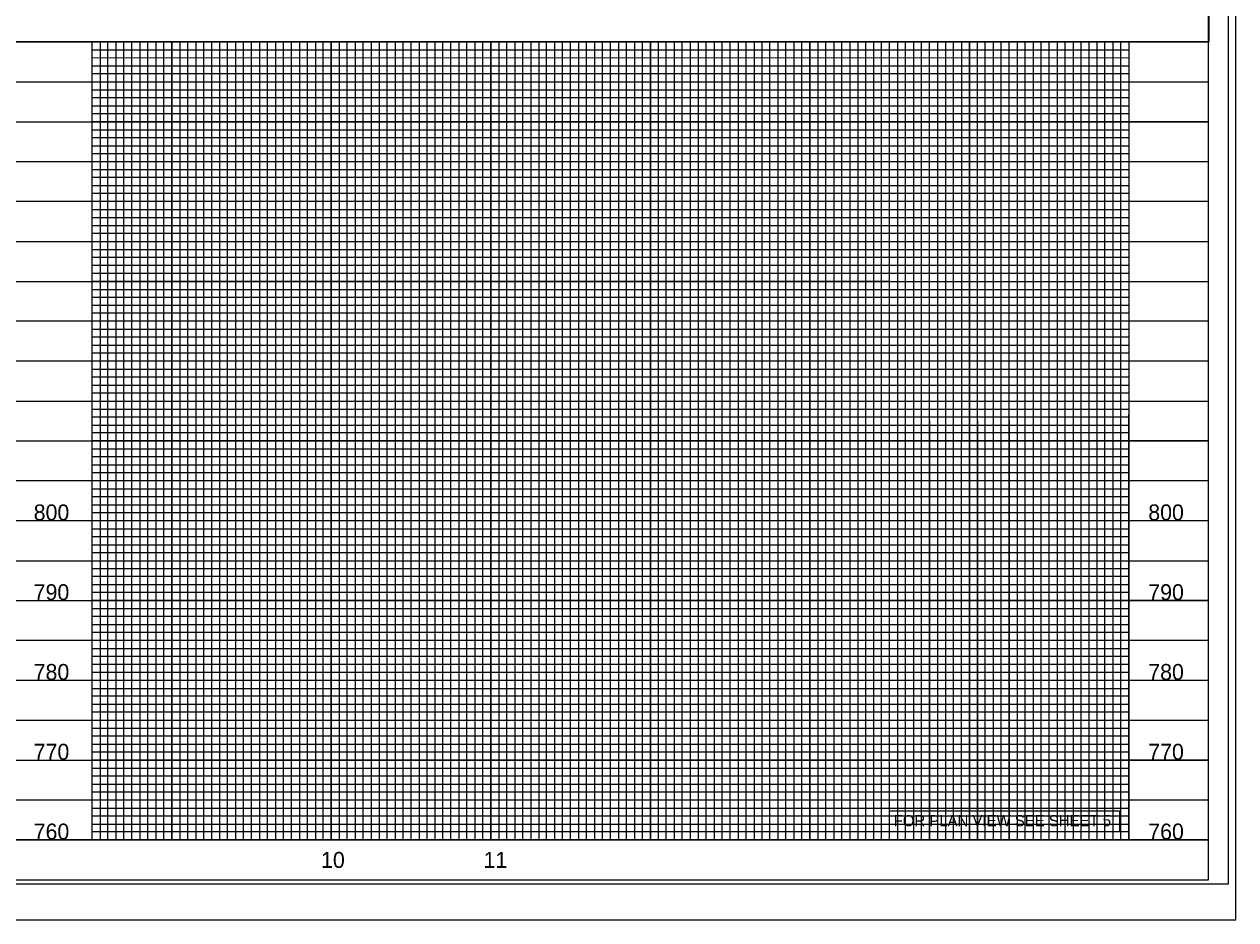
# Model space of a CAD drawing. Extents: x 1755181 to 1757273, y 729911 to 735411.
# Drawn here: x 1756105 to 1756865, y 729911 to 730472 of the extents above; entities that cross this region are included whole.
import ezdxf

# ---------------------------------------------------------------- set-up
doc = ezdxf.new("R2010")
doc.units = 0
for name, color, linetype in [('Exist Vertical Profile Horizontal Axis Label Major', 7, 'Continuous'), ('Exist Vertical Profile Vertical Axis Label', 7, 'Continuous'), ('Prop Grid Mask', 7, 'Continuous'), ('Prop VPI Label', 7, 'Continuous'), ('Scratch_Level_3', 7, 'Continuous'), ('Sheet Cutting Line CELL', 7, 'Continuous'), ('Sheet DOT Grid CELL', 7, 'Continuous'), ('Sheet Plot Border Inside CELL', 7, 'Continuous'), ('Sheet Plot Border Outside CELL', 7, 'Continuous'), ('Sheet Profile CELL', 7, 'Continuous'), ('Sheet Profile Grid Major CELL', 7, 'Continuous'), ('Sheet Profile Grid Middle CELL', 7, 'Continuous'), ('Sheet Profile Grid Minor CELL', 7, 'Continuous')]:
    doc.layers.add(name, color=color, linetype=linetype)

msp = doc.modelspace()

# ---------------------------------------------------------------- linework, layer by layer
at = {"layer": 'Prop Grid Mask'}
msp.add_lwpolyline([(1756647.67, 729978.99), (1756791.8, 729978.99), (1756791.8, 729965.78), (1756647.67, 729965.78)], close=True, dxfattribs=at)
at = {"layer": 'Scratch_Level_3'}
for points in [[(1756097.67, 730460.78), (1756097.67, 730985.78), (1756647.63, 730985.78), (1756647.63, 730752.66), (1756847.68, 730752.66), (1756847.68, 730460.78)], [(1756097.67, 729960.78), (1756847.67, 729960.78), (1756847.67, 730460.78), (1756097.67, 730460.78)]]:
    msp.add_lwpolyline(points, close=True, dxfattribs=at)
at = {"layer": 'Sheet Cutting Line CELL'}
msp.add_line((1755180.67, 729910.78), (1756864.67, 729910.78), dxfattribs=at)
at = {"layer": 'Sheet DOT Grid CELL'}
for p, q in [((1755347.67, 730460.78), (1756847.56, 730460.78)), ((1756147.67, 729960.78), (1756147.67, 730460.78)), ((1756197.67, 729960.78), (1756197.67, 730460.78)), ((1756247.67, 729960.78), (1756247.67, 730460.78)), ((1756297.67, 729960.78), (1756297.67, 730460.78)), ((1756347.67, 729960.78), (1756347.67, 730460.78)), ((1756397.67, 729960.78), (1756397.67, 730460.78)), ((1756447.67, 729960.78), (1756447.67, 730460.78)), ((1756497.67, 729960.78), (1756497.67, 730460.78)), ((1756547.67, 729960.78), (1756547.67, 730460.78)), ((1756597.67, 729960.78), (1756597.67, 730460.78)), ((1756697.67, 729960.78), (1756697.67, 730460.78)), ((1756747.67, 729960.78), (1756747.67, 730460.78)), ((1756847.66, 730410.78), (1756147.67, 730410.78)), ((1756647.62, 730360.78), (1756147.67, 730360.78)), ((1756647.67, 729960.78), (1756647.67, 730323.23)), ((1756647.67, 730310.78), (1756147.67, 730310.78)), ((1756797.67, 729960.78), (1756797.67, 730227.66)), ((1756847.67, 730210.78), (1756147.67, 730210.78)), ((1756847.67, 730160.78), (1756147.67, 730160.78)), ((1756847.67, 730110.78), (1756147.67, 730110.78)), ((1756847.67, 730060.78), (1756147.67, 730060.78)), ((1756847.67, 730010.78), (1756147.67, 730010.78))]:
    msp.add_line(p, q, dxfattribs=at)
at = {"layer": 'Sheet Plot Border Inside CELL'}
msp.add_lwpolyline([(1755193.67, 729933.23), (1756860.17, 729933.23), (1756860.17, 730988.33), (1755193.67, 730988.33)], close=True, dxfattribs=at)
at = {"layer": 'Sheet Plot Border Outside CELL'}
msp.add_lwpolyline([(1755180.67, 729910.78), (1756864.67, 729910.78), (1756864.67, 731010.78), (1755180.67, 731010.78)], close=True, dxfattribs=at)
at = {"layer": 'Sheet Profile CELL'}
for p, q in [((1755347.67, 730460.78), (1756847.67, 730460.78)), ((1756847.67, 729960.78), (1755347.67, 729960.78)), ((1755347.67, 729935.78), (1756847.67, 729935.78))]:
    msp.add_line(p, q, dxfattribs=at)
msp.add_lwpolyline([(1756847.67, 730985.78), (1755347.67, 730985.78), (1755347.67, 729935.78), (1756847.67, 729935.78)], close=True, dxfattribs=at)
at = {"layer": 'Sheet Profile Grid Major CELL'}
for p, q in [((1756147.67, 730460.78), (1756197.67, 730460.78)), ((1756247.67, 730460.78), (1756297.67, 730460.78)), ((1756347.67, 730460.78), (1756397.67, 730460.78)), ((1756447.67, 730460.78), (1756497.67, 730460.78)), ((1756547.67, 730460.78), (1756597.67, 730460.78)), ((1756647.67, 730460.78), (1756697.67, 730460.78)), ((1756747.67, 730460.78), (1756797.67, 730460.78)), ((1756747.47, 729960.67), (1756747.47, 729960.67))]:
    msp.add_line(p, q, dxfattribs=at)
for points in [[(1756097.67, 729960.78), (1756147.67, 729960.78), (1756147.67, 730460.78), (1756197.67, 730460.78), (1756197.67, 729960.78), (1756247.67, 729960.78), (1756247.67, 730460.78), (1756297.67, 730460.78), (1756297.67, 729960.78), (1756347.67, 729960.78), (1756347.67, 730460.78), (1756397.67, 730460.78), (1756397.67, 729960.78), (1756447.67, 729960.78), (1756447.67, 730460.78), (1756497.67, 730460.78), (1756497.67, 729960.78), (1756547.67, 729960.78), (1756547.67, 730460.78), (1756597.67, 730460.78), (1756597.67, 729960.78), (1756647.67, 729960.78), (1756647.67, 730460.78), (1756673.97, 730460.78)], [(1756697.67, 730460.78), (1756697.67, 729960.78), (1756747.67, 729960.78), (1756747.67, 729960.78), (1756747.67, 730460.78)], [(1756797.67, 730460.78), (1756797.67, 729960.78), (1756847.67, 729960.78), (1756847.67, 730310.78)], [(1755347.67, 730410.78), (1756847.71, 730410.78)], [(1756847.71, 730360.78), (1755347.67, 730360.78), (1755347.67, 730310.78), (1756847.71, 730310.78)], [(1756847.67, 730260.78), (1755347.67, 730260.78), (1755347.67, 730210.78), (1756847.67, 730210.78)], [(1756847.67, 730160.78), (1755347.67, 730160.78), (1755347.67, 730110.78), (1756847.67, 730110.78)], [(1756847.67, 730060.78), (1755347.67, 730060.78), (1755347.67, 730060.78), (1755347.67, 730010.78), (1756847.67, 730010.78)], [(1756847.67, 729960.78), (1755347.67, 729960.78)]]:
    msp.add_lwpolyline(points, dxfattribs=at)
at = {"layer": 'Sheet Profile Grid Middle CELL'}
for p, q in [((1756172.67, 729960.78), (1756172.67, 730460.78)), ((1756222.67, 730460.78), (1756222.67, 729960.78)), ((1756272.67, 729960.78), (1756272.67, 730460.78)), ((1756322.67, 730460.78), (1756322.67, 729960.78)), ((1756372.67, 729960.78), (1756372.67, 730460.78)), ((1756422.67, 730460.78), (1756422.67, 729960.78)), ((1756472.67, 729960.78), (1756472.67, 730460.78)), ((1756522.67, 730460.78), (1756522.67, 729960.78)), ((1756572.67, 729960.78), (1756572.67, 730460.78)), ((1756622.67, 730460.78), (1756622.67, 729960.78)), ((1756672.67, 729960.78), (1756672.67, 730460.78)), ((1755347.67, 730435.78), (1756847.66, 730435.78))]:
    msp.add_line(p, q, dxfattribs=at)
for points in [[(1756672.67, 730223.58), (1756672.67, 729960.78), (1756722.67, 729960.78), (1756722.67, 730460.78)], [(1756722.67, 730223.58), (1756722.67, 729960.78), (1756772.67, 729960.78), (1756772.67, 730460.78)], [(1756847.71, 730385.78), (1755347.67, 730385.78), (1755347.67, 730335.78), (1756847.71, 730335.78)], [(1756847.66, 730285.78), (1755347.67, 730285.78), (1755347.67, 730235.78), (1756847.67, 730235.78)], [(1756847.67, 730185.78), (1755347.67, 730185.78), (1755347.67, 730135.78), (1756847.67, 730135.78)], [(1756847.67, 730085.78), (1755347.67, 730085.78), (1755347.67, 730035.78), (1756847.67, 730035.78)], [(1756847.67, 729985.78), (1755347.67, 729985.78)]]:
    msp.add_lwpolyline(points, dxfattribs=at)
at = {"layer": 'Sheet Profile Grid Minor CELL'}
for p, q in [((1756152.67, 730460.78), (1756152.67, 729960.78)), ((1756157.67, 729960.78), (1756157.67, 730460.78)), ((1756162.67, 730460.78), (1756162.67, 729960.78)), ((1756167.67, 729960.78), (1756167.67, 730460.78)), ((1756177.67, 730460.78), (1756177.67, 729960.78)), ((1756182.67, 729960.78), (1756182.67, 730460.78)), ((1756187.67, 730460.78), (1756187.67, 729960.78)), ((1756192.67, 729960.78), (1756192.67, 730460.78)), ((1756202.67, 730460.78), (1756202.67, 729960.78)), ((1756207.67, 729960.78), (1756207.67, 730460.78)), ((1756212.67, 730460.78), (1756212.67, 729960.78)), ((1756217.67, 729960.78), (1756217.67, 730460.78)), ((1756227.67, 730460.78), (1756227.67, 729960.78)), ((1756147.67, 730455.78), (1756797.71, 730455.78)), ((1756797.71, 730450.78), (1756147.67, 730450.64)), ((1756147.67, 730445.78), (1756797.71, 730445.78)), ((1756797.66, 730325.78), (1756147.67, 730325.78)), ((1756797.71, 730320.78), (1756147.67, 730320.78)), ((1756797.71, 730315.78), (1756147.67, 730315.78)), ((1756147.67, 730305.78), (1756797.71, 730305.78)), ((1756797.71, 730300.78), (1756147.67, 730300.78)), ((1756147.67, 730295.78), (1756797.66, 730295.78)), ((1756797.66, 730275.78), (1756147.67, 730275.78)), ((1756147.67, 730270.78), (1756797.66, 730270.78)), ((1756797.67, 730250.78), (1756147.67, 730250.78)), ((1756147.67, 730245.78), (1756797.67, 730245.78)), ((1756797.67, 730225.78), (1756147.67, 730225.78)), ((1756147.67, 730220.78), (1756797.67, 730220.78)), ((1756797.67, 730215.78), (1756147.67, 730215.78)), ((1756147.67, 730205.78), (1756797.67, 730205.78)), ((1756797.67, 730200.78), (1756147.67, 730200.78)), ((1756147.67, 730195.78), (1756797.67, 730195.78)), ((1756797.67, 730190.78), (1756147.67, 730190.78)), ((1756147.67, 730180.78), (1756797.67, 730180.78)), ((1756797.67, 730175.78), (1756147.67, 730175.78)), ((1756147.67, 730170.78), (1756797.67, 730170.78)), ((1756797.67, 730165.78), (1756147.67, 730165.78)), ((1756147.67, 730155.78), (1756797.67, 730155.78)), ((1756797.67, 730150.78), (1756147.67, 730150.78)), ((1756147.67, 730145.78), (1756797.67, 730145.78)), ((1756797.67, 730140.78), (1756147.67, 730140.78)), ((1756147.67, 730130.78), (1756797.67, 730130.78)), ((1756797.67, 730125.78), (1756147.67, 730125.78)), ((1756147.67, 730120.78), (1756797.67, 730120.78)), ((1756797.67, 730115.78), (1756147.67, 730115.78)), ((1756147.67, 730105.78), (1756797.67, 730105.78)), ((1756797.67, 730100.78), (1756147.67, 730100.78)), ((1756147.67, 730095.78), (1756797.67, 730095.78)), ((1756797.67, 730090.78), (1756147.67, 730090.78)), ((1756147.67, 730080.78), (1756797.67, 730080.78)), ((1756797.67, 730075.78), (1756147.67, 730075.78)), ((1756797.67, 730070.78), (1756147.67, 730070.78)), ((1756797.67, 730065.78), (1756147.67, 730065.78)), ((1756147.67, 730055.78), (1756797.67, 730055.78)), ((1756797.67, 730050.78), (1756147.67, 730050.78)), ((1756147.67, 730045.78), (1756797.67, 730045.78)), ((1756797.67, 730040.78), (1756147.67, 730040.78)), ((1756147.67, 730030.78), (1756797.67, 730030.78)), ((1756797.67, 730025.78), (1756147.67, 730025.78)), ((1756147.67, 730020.78), (1756797.67, 730020.78)), ((1756797.67, 730015.78), (1756147.67, 730015.78)), ((1756147.67, 730005.78), (1756797.67, 730005.78)), ((1756797.67, 730000.78), (1756147.67, 730000.78)), ((1756147.67, 729995.78), (1756797.67, 729995.78)), ((1756797.67, 729990.78), (1756147.67, 729990.78)), ((1756147.67, 729980.78), (1756797.67, 729980.78)), ((1756797.67, 729975.78), (1756147.67, 729975.78)), ((1756147.67, 729970.78), (1756797.67, 729970.78))]:
    msp.add_line(p, q, dxfattribs=at)
for points in [[(1756232.67, 729960.78), (1756232.67, 730460.78), (1756237.67, 730460.78), (1756237.67, 729960.78), (1756242.67, 729960.78), (1756242.67, 730460.78), (1756252.67, 730460.78), (1756252.67, 729960.78), (1756257.67, 729960.78), (1756257.67, 730460.78), (1756262.67, 730460.78), (1756262.67, 729960.78), (1756267.67, 729960.78), (1756267.67, 730460.78), (1756277.67, 730460.78), (1756277.67, 729960.78), (1756282.67, 729960.78), (1756282.67, 730460.78), (1756287.67, 730460.78), (1756287.67, 729960.78), (1756292.67, 729960.78), (1756292.67, 730460.78), (1756302.67, 730460.78), (1756302.67, 729960.78), (1756307.67, 729960.78), (1756307.67, 730460.78), (1756312.67, 730460.78), (1756312.67, 729960.78), (1756317.67, 729960.78), (1756317.67, 730460.78), (1756327.67, 730460.78), (1756327.67, 729960.78), (1756332.67, 729960.78), (1756332.67, 730460.78), (1756337.67, 730460.78), (1756337.67, 729960.78), (1756342.67, 729960.78), (1756342.67, 730460.78), (1756352.67, 730460.78), (1756352.67, 729960.78), (1756357.67, 729960.78), (1756357.67, 730460.78), (1756362.67, 730460.78), (1756362.67, 729960.78), (1756367.67, 729960.78), (1756367.67, 730460.78), (1756377.67, 730460.78), (1756377.67, 729960.78), (1756382.67, 729960.78), (1756382.67, 730460.78), (1756387.67, 730460.78), (1756387.67, 729960.78), (1756392.67, 729960.78), (1756392.67, 730460.78), (1756402.67, 730460.78), (1756402.67, 729960.78), (1756407.67, 729960.78), (1756407.67, 730460.78), (1756412.67, 730460.78), (1756412.67, 729960.78), (1756417.67, 729960.78), (1756417.67, 730460.78), (1756427.67, 730460.78), (1756427.67, 729960.78), (1756432.67, 729960.78), (1756432.67, 730460.78), (1756437.67, 730460.78), (1756437.67, 729960.78), (1756442.67, 729960.78), (1756442.67, 730460.78), (1756452.67, 730460.78), (1756452.67, 729960.78), (1756457.67, 729960.78), (1756457.67, 730460.78), (1756462.67, 730460.78), (1756462.67, 729960.78), (1756467.67, 729960.78), (1756467.67, 730460.78), (1756477.67, 730460.78), (1756477.67, 729960.78), (1756482.67, 729960.78), (1756482.67, 730460.78), (1756487.67, 730460.78), (1756487.67, 729960.78), (1756492.67, 729960.78), (1756492.67, 730460.78), (1756502.67, 730460.78), (1756502.67, 729960.78), (1756507.67, 729960.78), (1756507.67, 730460.78), (1756512.67, 730460.78), (1756512.67, 729960.78), (1756517.67, 729960.78), (1756517.67, 730460.78), (1756527.67, 730460.78), (1756527.67, 729960.78), (1756532.67, 729960.78), (1756532.67, 730460.78), (1756537.67, 730460.78), (1756537.67, 729960.78)], [(1756537.67, 729960.78), (1756542.67, 729960.78), (1756542.67, 730460.78), (1756552.67, 730460.78), (1756552.67, 729960.78), (1756557.67, 729960.78), (1756557.67, 730460.78), (1756562.67, 730460.78), (1756562.67, 729960.78), (1756567.67, 729960.78), (1756567.67, 730460.78), (1756577.67, 730460.78), (1756577.67, 729960.78), (1756582.67, 729960.78), (1756582.67, 730460.78), (1756587.67, 730460.78), (1756587.67, 729960.78), (1756592.67, 729960.78), (1756592.67, 730460.78), (1756602.67, 730460.78), (1756602.67, 729960.78), (1756607.67, 729960.78), (1756607.67, 730460.78), (1756612.67, 730460.78), (1756612.67, 729960.78), (1756617.67, 729960.78), (1756617.67, 730460.78), (1756627.67, 730460.78), (1756627.67, 729960.78), (1756632.67, 729960.78), (1756632.67, 730460.78), (1756637.67, 730460.78), (1756637.67, 729960.78), (1756642.67, 729960.78), (1756642.67, 730460.78), (1756652.67, 730460.78)], [(1756652.67, 730460.78), (1756652.67, 729960.78), (1756657.67, 729960.78), (1756657.67, 730460.78)], [(1756662.67, 730460.78), (1756662.67, 729960.78), (1756667.67, 729960.78), (1756667.67, 730460.78)], [(1756677.67, 730460.78), (1756677.67, 729960.78), (1756677.67, 729960.78), (1756682.67, 729960.78), (1756687.67, 729960.78), (1756687.67, 730460.78)], [(1756682.67, 730460.78), (1756682.67, 729960.78)], [(1756692.64, 730460.78), (1756692.57, 729960.83), (1756697.57, 729960.83), (1756702.67, 729960.78), (1756702.67, 730460.78)], [(1756702.67, 730223.58), (1756702.67, 729960.78), (1756707.67, 729960.78), (1756707.67, 730460.78)], [(1756712.67, 730460.78), (1756712.67, 729960.78), (1756717.67, 729960.78), (1756717.67, 730460.78)], [(1756727.67, 730460.78), (1756727.67, 729960.78), (1756732.67, 729960.78), (1756732.67, 730460.78)], [(1756737.67, 730460.78), (1756737.67, 729960.78), (1756742.67, 729960.78), (1756742.67, 730460.78)], [(1756752.67, 730460.78), (1756752.67, 729960.78), (1756757.67, 729960.78), (1756757.67, 730460.78)], [(1756762.67, 730460.78), (1756762.67, 729960.78), (1756767.67, 729960.78), (1756767.67, 730460.78)], [(1756777.67, 730460.78), (1756777.67, 729960.78), (1756782.67, 729960.78), (1756782.67, 730460.78)], [(1756787.67, 730460.78), (1756787.67, 729960.78), (1756792.67, 729960.78), (1756792.67, 730460.78)], [(1756797.71, 730440.78), (1756147.67, 730440.78)], [(1756147.67, 730430.78), (1756797.71, 730430.78)], [(1756797.66, 730425.78), (1756147.67, 730425.78)], [(1756147.67, 730420.78), (1756797.71, 730420.78)], [(1756797.71, 730415.78), (1756147.67, 730415.78)], [(1756147.67, 730405.78), (1756797.71, 730405.78)], [(1756797.71, 730400.78), (1756147.67, 730400.78)], [(1756147.67, 730395.78), (1756797.71, 730395.78)], [(1756797.71, 730390.78), (1756147.67, 730390.78)], [(1756147.67, 730380.78), (1756797.71, 730380.78)], [(1756797.71, 730375.78), (1756147.67, 730375.78)], [(1756147.67, 730370.78), (1756797.71, 730370.78)], [(1756797.71, 730365.78), (1756147.67, 730365.78)], [(1756147.67, 730355.78), (1756797.71, 730355.78)], [(1756797.71, 730350.68), (1756147.67, 730350.68)], [(1756147.67, 730345.78), (1756797.71, 730345.78)], [(1756797.71, 730340.78), (1756147.67, 730340.78)], [(1756147.67, 730330.78), (1756797.71, 730330.78)], [(1756797.66, 730290.78), (1756147.67, 730290.78)], [(1756147.67, 730280.78), (1756797.66, 730280.78)], [(1756797.66, 730265.78), (1756147.67, 730265.78)], [(1756147.67, 730255.78), (1756797.67, 730255.78)], [(1756797.67, 730240.78), (1756147.67, 730240.78)], [(1756147.67, 730230.78), (1756797.67, 730230.78)], [(1756797.67, 729965.78), (1756147.67, 729965.78)]]:
    msp.add_lwpolyline(points, dxfattribs=at)

# ---------------------------------------------------------------- texts
at = {"layer": 'Exist Vertical Profile Horizontal Axis Label Major'}
for s, p in [('10', (1756291.25, 729943.28)), ('11', (1756393.09, 729943.28))]:
    msp.add_text(s, height=10, dxfattribs=at).set_placement(p)
at = {"layer": 'Exist Vertical Profile Vertical Axis Label'}
for s, p in [('800', (1756111.1, 730161.03)), ('800', (1756809.82, 730161.03)), ('790', (1756111.1, 730111.03)), ('790', (1756809.82, 730111.03)), ('780', (1756111.1, 730061.03)), ('780', (1756809.82, 730061.03)), ('770', (1756111.1, 730011.03)), ('770', (1756809.82, 730011.03)), ('760', (1756111.1, 729961.03)), ('760', (1756809.82, 729961.03))]:
    msp.add_text(s, height=10, dxfattribs=at).set_placement(p)
at = {"layer": 'Prop VPI Label'}
msp.add_text('FOR PLAN VIEW SEE SHEET 5', height=7, dxfattribs=at).set_placement((1756650.21, 729969.37))

doc.saveas('drawing.dxf')
